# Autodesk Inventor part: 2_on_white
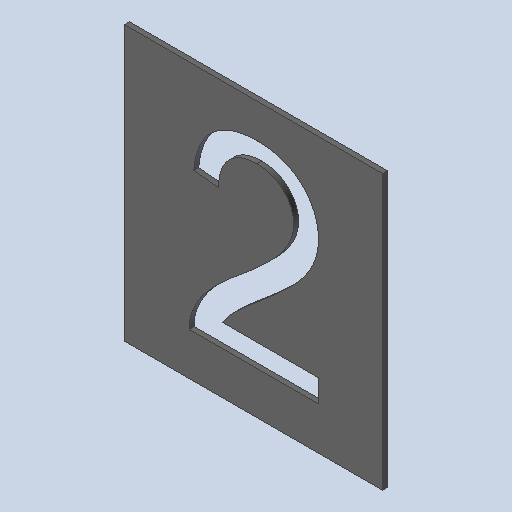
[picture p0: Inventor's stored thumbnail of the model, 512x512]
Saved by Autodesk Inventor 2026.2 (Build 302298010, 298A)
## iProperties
Created: 2026-10
Part Number: 2_on_white
Material: Générique
Document SubType Name: Modeling
Designer: mel
Density: 1 g/cm^3
Appearance: Par défaut
Author: mel
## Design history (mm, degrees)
feature "Base1"
node "Solide1"
